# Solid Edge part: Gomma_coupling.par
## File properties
Author: f_grande
Template: Normal.par
Last saved by: f_grande
Revision: 4
Application: Solid Edge
Densità: 1385,000 kg/m^3
Precisione: 0,990
Tipo di contenuto documento: 0
Material: PVC
Stile della faccia: Marroncino
Stile di riempimento: ANSI34(Plastica)
Stile virtuale: Marroncino (lucido)
Coef. of Thermal Exp: 0.0
Thermal Conductivity: 1.5
Specific Heat: 0.0
Modulus of Elasticity: 2757902.8
Poisson's Ratio: 0.4
Yield Stress: 6894757.0
Ultimate Stress: 0.0
Elongation: 0.0
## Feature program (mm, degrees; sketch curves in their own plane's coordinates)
sketch for "unnamed Protrusion 1" plane through (0, 0, 0) normal (0, 0, 1) x-axis (1, 0, 0)
  circle centre (0, 0) radius 13.75
extrude "unnamed Protrusion 1" add finite 10 along +normal
sketch for "ExtrudedCutout_1" #1 plane through (0, 0, 10) normal (0, 0, 1) x-axis (0, 1, 0)
sketch for "ExtrudedCutout_1" #2 plane through (0, 0, 10) normal (0, 0, 1) x-axis (0, 1, 0)
  line (-3.3809, 7.2505) -> (-5.811, 12.4617)
  arc centre (0, 0) radius 13.75 from (-5.811, 12.4617) to (5.811, 12.4617) cw
  line (3.3809, 7.2505) -> (5.811, 12.4617)
sketch for "ExtrudedCutout_1" #3 plane through (0, 0, 10) normal (0, 0, 1) x-axis (0, 1, 0)
  line (7.2505, 3.3809) -> (12.4617, 5.811)
  arc centre (0, 0) radius 13.75 from (12.4617, 5.811) to (12.4617, -5.811) cw
  line (7.2505, -3.3809) -> (12.4617, -5.811)
  arc centre (0, 0) radius 8 from (7.2505, 3.3809) to (7.2505, -3.3809) cw
sketch for "ExtrudedCutout_1" #4 plane through (0, 0, 10) normal (0, 0, 1) x-axis (0, 1, 0)
  line (3.3809, -7.2505) -> (5.811, -12.4617)
  line (-3.3809, -7.2505) -> (-5.811, -12.4617)
  arc centre (0, 0) radius 8 from (3.3809, -7.2505) to (-3.3809, -7.2505) cw
extrude "ExtrudedCutout_1" cut finite 10 along -normal
fillet "Rotondo_1" radius 0.5
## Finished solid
Body 1: solid body, 34 faces, 96 edges, 64 vertices.
  Faces by surface: cylinder 24, plane 10
  Edges by curve: circle 48, line 48
Bounding box of the edges (mm): 24.577 x 24.666 x 10.000, from (-12.2887, -12.3776, 0) to (12.2887, 12.2887, 10).
Cylindrical faces by radius (mm): R0.5 x16, R8 x4, R13.75 x4
Planar faces by outward normal: +z 1, -z 1, oblique 8
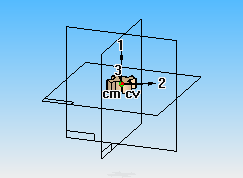
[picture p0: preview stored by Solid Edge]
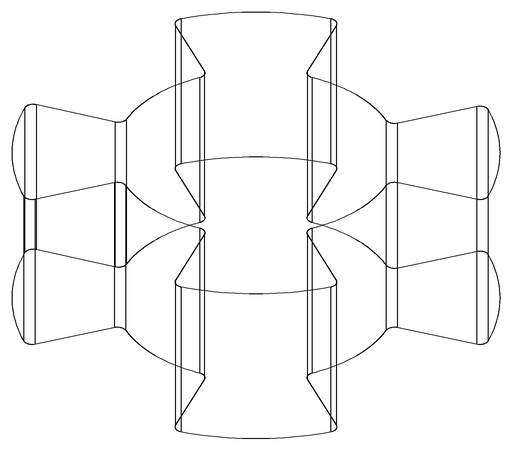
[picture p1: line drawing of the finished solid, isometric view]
